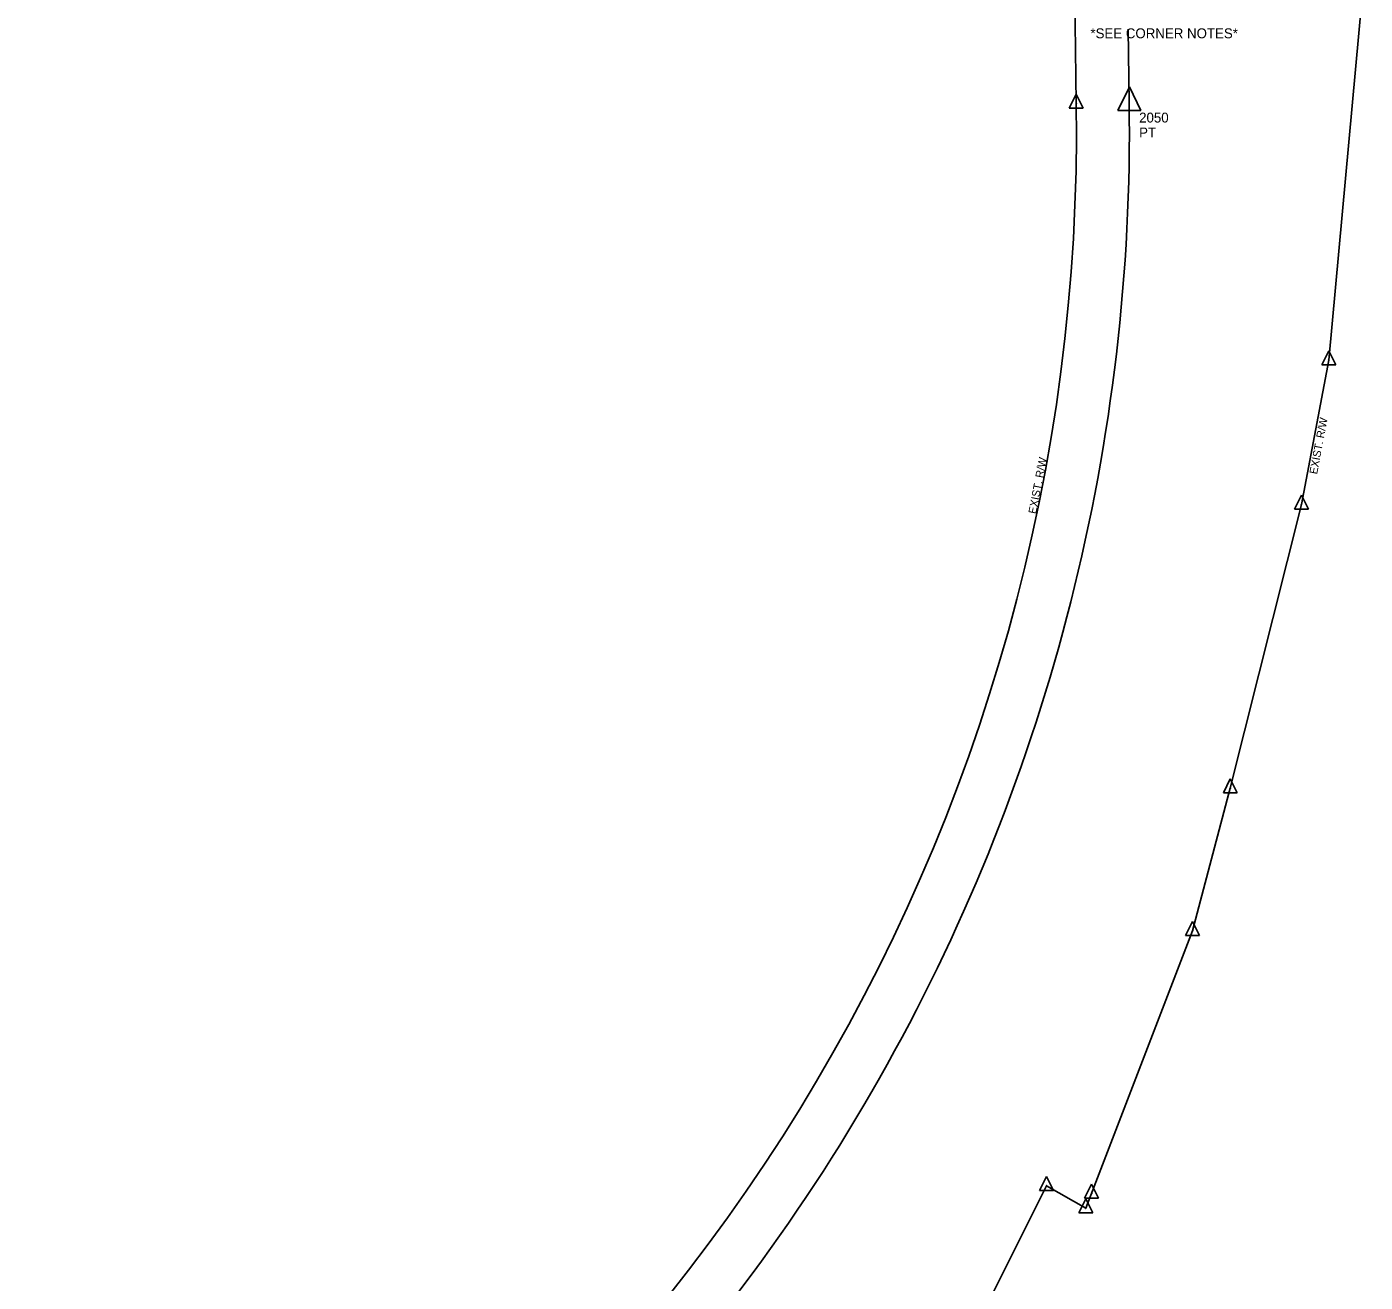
# Model space of a CAD drawing. Extents: x 1674300 to 1677561, y 225056 to 231852.
# Drawn here: x 1676544 to 1677556, y 228119 to 229068 of the extents above; entities that cross this region are included whole.
import ezdxf

# ---------------------------------------------------------------- set-up
doc = ezdxf.new("R2010")
doc.units = 0
for name, color, linetype in [('R_Annotation', 7, 'Continuous'), ('S_CAL_CORNER', 7, 'Continuous'), ('S_CAL_CORNER_ANNOT', 7, 'Continuous'), ('S_EXIST_ROW', 7, 'Continuous'), ('S_EXISTING_ALIGNMENT', 7, 'Continuous')]:
    doc.layers.add(name, color=color, linetype=linetype)

msp = doc.modelspace()

# ---------------------------------------------------------------- linework, layer by layer
at = {"layer": 'S_CAL_CORNER'}
for p, q in [((1677377.2, 229023.1), (1677368.4, 229005.3)), ((1677377.2, 229023.1), (1677368.4, 229005.3)), ((1677377.2, 229023.1), (1677368.4, 229005.3)), ((1677377.2, 229023.1), (1677368.4, 229005.3)), ((1677377.2, 229023.1), (1677385.9, 229005.3)), ((1677377.2, 229023.1), (1677385.9, 229005.3)), ((1677377.2, 229023.1), (1677385.9, 229005.3)), ((1677377.2, 229023.1), (1677385.9, 229005.3)), ((1677368.4, 229005.3), (1677385.9, 229005.3)), ((1677368.4, 229005.3), (1677385.9, 229005.3)), ((1677368.4, 229005.3), (1677385.9, 229005.3)), ((1677368.4, 229005.3), (1677385.9, 229005.3))]:
    msp.add_line(p, q, dxfattribs=at)
at = {"layer": 'S_EXIST_ROW'}
for p, q in [((1677337.1, 229010.5), (1677299.9, 231497.5)), ((1677527.9, 228816.5), (1677555.5, 229117)), ((1677337.1, 229017.6), (1677331.8, 229006.9)), ((1677337.1, 229017.6), (1677342.3, 229006.9)), ((1677331.8, 229006.9), (1677342.3, 229006.9)), ((1677337.1, 229010.5), (1677337.1, 229010.5)), ((1677527.9, 228823.5), (1677522.6, 228812.9)), ((1677527.9, 228823.5), (1677533.2, 228812.9)), ((1677507.3, 228707.4), (1677527.9, 228816.5)), ((1677522.6, 228812.9), (1677533.2, 228812.9)), ((1677527.9, 228816.5), (1677527.9, 228816.5)), ((1677507.3, 228714.5), (1677502, 228703.9)), ((1677507.3, 228714.5), (1677512.5, 228703.9)), ((1677453.5, 228492.9), (1677507.3, 228707.4)), ((1677502, 228703.9), (1677512.5, 228703.9)), ((1677507.3, 228707.4), (1677507.3, 228707.4)), ((1677453.5, 228500), (1677448.3, 228489.3)), ((1677453.5, 228500), (1677458.8, 228489.3)), ((1677425, 228385.1), (1677453.5, 228492.9)), ((1677448.3, 228489.3), (1677458.8, 228489.3)), ((1677453.5, 228492.9), (1677453.5, 228492.9)), ((1677344.3, 228175.4), (1677425, 228385.1)), ((1677425, 228392.2), (1677419.7, 228381.6)), ((1677425, 228392.2), (1677430.2, 228381.6)), ((1677425, 228385.1), (1677425, 228385.1)), ((1677419.7, 228381.6), (1677430.2, 228381.6)), ((1677264.8, 228093.1), (1677314.7, 228192.4)), ((1677314.7, 228199.5), (1677309.4, 228188.9)), ((1677314.7, 228199.5), (1677319.9, 228188.9)), ((1677314.7, 228192.4), (1677314.7, 228192.4)), ((1677314.7, 228192.4), (1677344.3, 228175.4)), ((1677348.6, 228193.6), (1677343.3, 228183)), ((1677348.6, 228193.6), (1677353.8, 228183)), ((1677309.4, 228188.9), (1677319.9, 228188.9)), ((1677344.3, 228182.5), (1677339, 228171.9)), ((1677343.3, 228183), (1677353.8, 228183)), ((1677344.3, 228182.5), (1677349.6, 228171.9)), ((1677348.6, 228186.5), (1677348.6, 228186.5)), ((1677344.3, 228175.4), (1677344.3, 228175.4)), ((1677339, 228171.9), (1677349.6, 228171.9))]:
    msp.add_line(p, q, dxfattribs=at)
for centre, radius in [((1677337.1, 229010.5), 0.18), ((1677337.1, 229010.5), 0.09), ((1677527.9, 228816.5), 0.18), ((1677527.9, 228816.5), 0.09), ((1677507.3, 228707.4), 0.18), ((1677507.3, 228707.4), 0.09), ((1677453.5, 228492.9), 0.18), ((1677453.5, 228492.9), 0.09), ((1677425, 228385.1), 0.18), ((1677425, 228385.1), 0.09), ((1677314.7, 228192.4), 0.18), ((1677314.7, 228192.4), 0.09), ((1677348.6, 228186.5), 0.18), ((1677348.6, 228186.5), 0.09), ((1677344.3, 228175.4), 0.18), ((1677344.3, 228175.4), 0.09)]:
    msp.add_circle(centre, radius, dxfattribs=at)
msp.add_arc((1675926.7, 228989.4), 1410.5, 295.9436, 0.8568, dxfattribs=at)
at = {"layer": 'S_EXISTING_ALIGNMENT'}
msp.add_line((1677377.1, 229011.1), (1677376.2, 229066.8), dxfattribs=at)
for start, end in [(345.8132, 0.8568), (315.9886, 345.8132)]:
    msp.add_arc((1675926.7, 228989.4), 1450.5, start, end, dxfattribs=at)

# ---------------------------------------------------------------- texts
at = {"layer": 'R_Annotation'}
for rotation, p in [(79.2793, (1677519.1, 228729.9)), (79.1028, (1677306.7, 228699.9))]:
    msp.add_text('EXIST. R/W', height=6, rotation=rotation, dxfattribs=at).set_placement(p)
at = {"layer": 'S_CAL_CORNER_ANNOT'}
for s, p in [('*SEE CORNER NOTES*', (1677347.8, 229059.8)), ('2050', (1677384.6, 228996.1)), ('2050', (1677384.6, 228996.1)), ('2050', (1677384.6, 228996.1)), ('2050', (1677384.6, 228996.1)), ('PT', (1677384.6, 228984.8)), ('PT', (1677384.6, 228984.8)), ('PT', (1677384.6, 228984.8)), ('PT', (1677384.6, 228984.8))]:
    msp.add_text(s, height=7.5, dxfattribs=at).set_placement(p)

doc.saveas('drawing.dxf')
